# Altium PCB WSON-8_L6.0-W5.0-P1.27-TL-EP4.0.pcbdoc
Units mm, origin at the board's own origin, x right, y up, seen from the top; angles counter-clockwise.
Board outline 20.51 x 17.85 mm, 2 copper layers (Top Layer, Bottom Layer), stack 0 mm thick; 1 components, 0 nets, 9 pads, 0 vias.
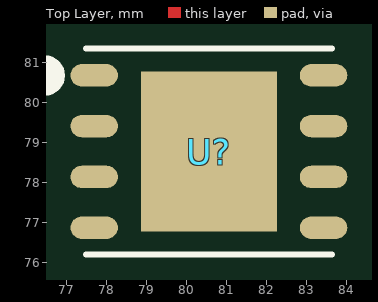
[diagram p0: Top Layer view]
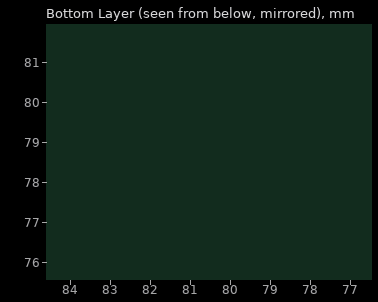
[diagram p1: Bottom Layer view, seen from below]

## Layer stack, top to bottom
Top Layer: signal copper (thickness not stored)
Bottom Layer: signal copper (thickness not stored)

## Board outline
90.36,69.85 69.85,69.85 69.85,87.702 90.36,87.702

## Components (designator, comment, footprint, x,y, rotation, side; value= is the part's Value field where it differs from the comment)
U? "" WSON-8_L6.0-W5.0-P1.27-TL-EP4.0 80.55,78.776 r0 top

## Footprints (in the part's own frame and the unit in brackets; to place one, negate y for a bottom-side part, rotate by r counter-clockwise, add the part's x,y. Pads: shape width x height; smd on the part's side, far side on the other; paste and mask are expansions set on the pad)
WSON-8_L6.0-W5.0-P1.27-TL-EP4.0 [mm]
  oval 1.185x0.56 smd: 1(-2.867,1.905) 2(-2.867,0.635) 3(-2.867,-0.635) 4(-2.867,-1.905) 5(2.867,-1.905) 6(2.867,-0.635) 7(2.867,0.635) 8(2.867,1.905)
  rect 3.4x4 smd: 9(0,0)
  silkscreen extent -4.35,-2.58 3.08,2.58

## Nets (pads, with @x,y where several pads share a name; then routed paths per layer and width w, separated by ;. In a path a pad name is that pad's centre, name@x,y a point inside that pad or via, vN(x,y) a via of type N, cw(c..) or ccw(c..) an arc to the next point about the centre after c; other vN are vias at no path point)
pads on no net: U?.1 U?.2 U?.3 U?.4 U?.5 U?.6 U?.7 U?.8 U?.9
